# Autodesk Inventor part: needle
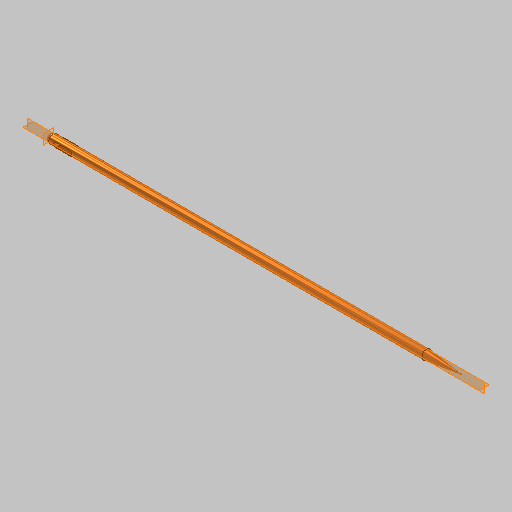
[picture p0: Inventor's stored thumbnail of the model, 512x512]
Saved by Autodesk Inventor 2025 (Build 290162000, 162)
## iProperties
Created: 2025-01
Part Number: needle
Material: Gold
Document SubType Name: Modeling
Designer: dansp
Density: 19.3 g/cm^3
Appearance: Metal 1600F Hot
Mass: 0.641696 g
Surface Area: 1.35923 cm^2
Volume: 0.0332485 cm^3
Author: dansp
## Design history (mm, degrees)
sketch "Sketch1"
  geometry: L1 (0, 0.6)-(0, -0.1) reference; L2 (-9, 0)-(54, 0) reference; L3 (0, 0)-(0, 0.5); L4 (0, 0.5)-(45, 0.5); L5 (45, 0.5)-(45, 0); L6 (45, 0)-(41, 0.5)
  constraints: 8 end point, 3 point on line, 1 horizontal, 1 perpendicular
  dimensions: "d0" = 1 diameter of L4 L2; "d1" = 4 horizontal distance of L5.end L6.end; "d2" = 45 distance of L3.end L4.end
revolve "Revolution1" sketch "Sketch1" stored, may be unused: angle "d3" = 90 deg
sketch "Sketch2"
  geometry: L1 (1.25, 0)-(2.75, 0); L2 (1.25, -0.25)-(2.75, -0.25); L3 (2.75, 0.25)-(1.25, 0.25); L4 (0, 0.7)-(0, -0.7) reference; L5 (-9, 0)-(54, 0) reference; A1 r 0.25 centre (1.25, 0) between (1.25, 0.25) and (1.25, -0.25); A2 r 0.25 centre (2.75, 0) between (2.75, -0.25) and (2.75, 0.25); 4 further points
  constraints: 8 end point, 6 point on circle, 4 tangent, 2 centre point, 1 horizontal, 1 midpoint, 1 parallel, 1 point on line
  dimensions: "d4" = 2 distance of point (1, 0) point (3, 0); "d5" = 1 distance from line of point (1, 0) L4; "d6" = 0.5 distance between parallel lines of L2 L3
extrude "Extrusion1" cut sketch "Sketch2" extent not by distance; stored distance "d7" = 0; taper "d8" = 0 deg
fillet "Fillet1" dims "d9" = 0.5
body "Solid1"
